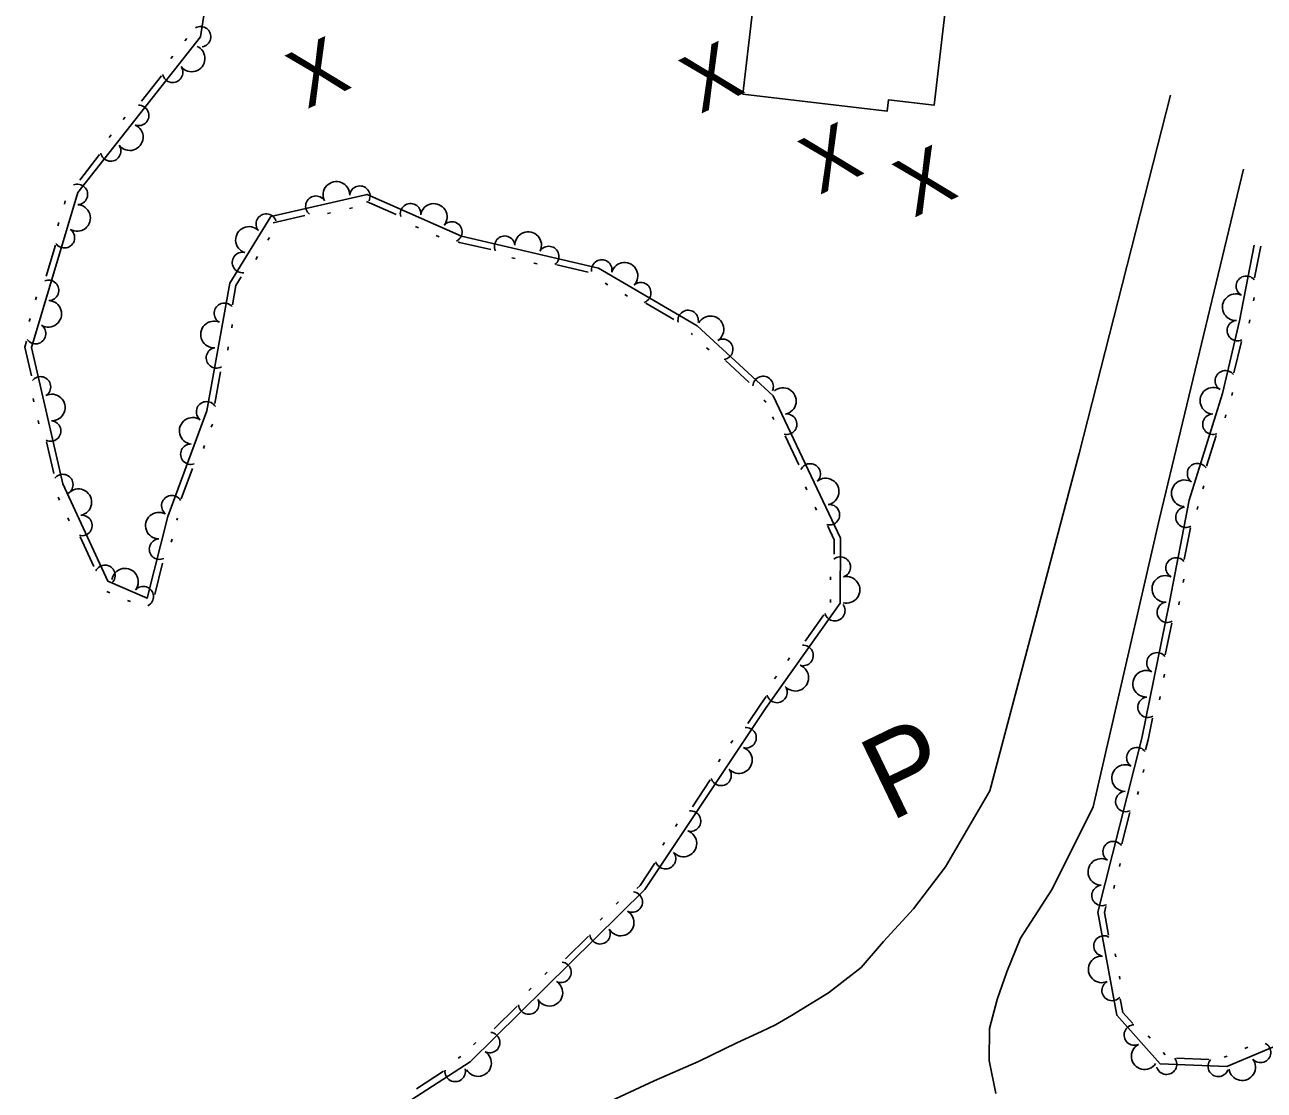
# Model space of a CAD drawing. Extents: x 2030130 to 2036320, y 723205 to 762423.
# Drawn here: x 2033439.8 to 2033597.2, y 761367.6 to 761502.9 of the extents above; entities that cross this region are included whole.
import ezdxf

# ---------------------------------------------------------------- set-up
doc = ezdxf.new("R2010")
doc.units = 0
for name, color, linetype in [('Draft_Station Labels Major', 7, 'Continuous'), ('Draft_Station Tics Major', 7, 'Continuous'), ('Exist Terrain Model Ground Surface', 7, 'Continuous'), ('Prop Horizontal Alignment Ramp', 7, 'Continuous')]:
    doc.layers.add(name, color=color, linetype=linetype)

msp = doc.modelspace()

# ---------------------------------------------------------------- linework, layer by layer
at = {"layer": 'Draft_Station Labels Major'}
for points in [[(2033525.39, 761371.23), (2033530.26, 761373.62), (2033533.37, 761375.05), (2033535.15, 761375.9), (2033537.18, 761377.07), (2033541.91, 761379.95), (2033546.04, 761383.19), (2033548.86, 761386.5), (2033552.7, 761390.64), (2033556.75, 761395.98), (2033562.4, 761405.6), (2033573.75, 761448.47), (2033585.35, 761493.96)], [(2033594.61, 761484.55), (2033583.93, 761440.18), (2033575.51, 761403.57), (2033570.32, 761393.14), (2033566.29, 761386.89), (2033564.53, 761382.64), (2033563.33, 761379.11), (2033562.33, 761375.43), (2033562.32, 761371.35), (2033563.15, 761367.2)], [(2033450.49, 761331), (2033472.55, 761343.63), (2033483.7, 761350.58), (2033494.36, 761356.54), (2033502.08, 761360.39), (2033511.2, 761364.83), (2033519.73, 761368.8), (2033525.39, 761371.23)]]:
    msp.add_lwpolyline(points, dxfattribs=at)
at = {"layer": 'Draft_Station Tics Major'}
for points in [[(2033464.52, 761516.87), (2033462.13, 761501.38), (2033446.55, 761481.58), (2033440.64, 761461.92), (2033444.62, 761444.59), (2033450.33, 761432.22), (2033455.34, 761430.07), (2033457.97, 761440.46), (2033462.94, 761453.88), (2033465.84, 761470.1), (2033471.07, 761478.54), (2033483.27, 761481.34), (2033495.28, 761476.04), (2033512.68, 761472), (2033525.2, 761464.67), (2033534.87, 761455.78), (2033543.43, 761437.68), (2033543.36, 761429.44), (2033533.88, 761416.05), (2033518.58, 761393.08), (2033496.38, 761371.21), (2033467.55, 761352.57)], [(2033460.39, 761501.16), (2033460.14, 761500.84)], [(2033458.62, 761498.91), (2033458.36, 761498.59)], [(2033457.16, 761496.4), (2033454.63, 761493.18)], [(2033452.53, 761491.17), (2033452.28, 761490.85)], [(2033450.76, 761488.92), (2033450.5, 761488.59)], [(2033449.3, 761486.41), (2033446.77, 761483.18)], [(2033444.94, 761480.52), (2033444.83, 761480.13)], [(2033481.04, 761479.57), (2033481.44, 761479.66)], [(2033483.21, 761480.47), (2033486.96, 761478.82)], [(2033471.36, 761477.76), (2033475.35, 761478.68)], [(2033478.24, 761478.92), (2033478.64, 761479.02)], [(2033444.12, 761477.77), (2033444, 761477.38)], [(2033489.42, 761477.28), (2033489.8, 761477.12)], [(2033443.69, 761474.9), (2033442.51, 761470.98)], [(2033470.66, 761475.54), (2033470.87, 761475.89)], [(2033492.05, 761476.12), (2033492.43, 761475.96)], [(2033494.84, 761475.34), (2033495.02, 761475.26), (2033498.98, 761474.34)], [(2033595.98, 761474.92), (2033594.12, 761465.29), (2033591.93, 761456.09), (2033587.72, 761442.52), (2033585.19, 761429.56), (2033581.69, 761412.29), (2033576.1, 761390.21), (2033578.5, 761377.11), (2033584.04, 761370.93), (2033592.47, 761370.59), (2033608.49, 761377.33)], [(2033596.79, 761474.77), (2033596.01, 761470.74)], [(2033469.15, 761473.1), (2033469.36, 761473.45)], [(2033501.68, 761473.29), (2033502.08, 761473.2)], [(2033504.48, 761472.64), (2033504.88, 761472.55)], [(2033507.37, 761472.39), (2033511.36, 761471.47)], [(2033466.18, 761467.32), (2033466.62, 761469.8), (2033467.29, 761470.88)], [(2033513.53, 761470.08), (2033513.88, 761469.87)], [(2033516.01, 761468.63), (2033516.36, 761468.42)], [(2033441.29, 761468.35), (2033441.17, 761467.95)], [(2033518.69, 761467.53), (2033522.23, 761465.46)], [(2033595.95, 761468.25), (2033595.87, 761467.85)], [(2033440.46, 761465.6), (2033440.34, 761465.2)], [(2033595.4, 761465.43), (2033595.32, 761465.02)], [(2033466.08, 761464.42), (2033466.15, 761464.82)], [(2033524.46, 761463.67), (2033524.6, 761463.55)], [(2033440.03, 761462.73), (2033439.8, 761461.95), (2033440.63, 761458.32)], [(2033594.34, 761462.68), (2033593.39, 761458.69)], [(2033465.57, 761461.59), (2033465.64, 761462)], [(2033526.41, 761461.88), (2033526.72, 761461.6)], [(2033528.81, 761460.24), (2033531.83, 761457.47)], [(2033463.94, 761454.8), (2033464.66, 761458.84)], [(2033593.22, 761456.2), (2033593.13, 761455.8)], [(2033440.87, 761455.43), (2033440.96, 761455.03)], [(2033533.66, 761455.22), (2033533.96, 761454.95)], [(2033441.51, 761452.63), (2033441.6, 761452.23)], [(2033534.77, 761453.12), (2033534.94, 761452.75)], [(2033592.38, 761453.37), (2033592.26, 761452.98)], [(2033463.47, 761451.78), (2033463.62, 761452.16)], [(2033442.55, 761449.93), (2033443.47, 761445.93)], [(2033462.48, 761449.08), (2033462.62, 761449.47)], [(2033536.37, 761450.7), (2033538.12, 761447)], [(2033591.13, 761450.75), (2033589.92, 761446.83)], [(2033459.67, 761442.69), (2033461.09, 761446.53)], [(2033538.97, 761444.23), (2033539.15, 761443.85)], [(2033589.58, 761444.36), (2033589.46, 761443.97)], [(2033444.05, 761442.89), (2033444.22, 761442.51)], [(2033540.2, 761441.63), (2033540.38, 761441.26)], [(2033588.82, 761441.73), (2033588.74, 761441.33)], [(2033445.25, 761440.28), (2033445.42, 761439.91)], [(2033459.11, 761439.98), (2033459.14, 761440.1), (2033459.2, 761440.24)], [(2033541.8, 761439.21), (2033542.61, 761437.5), (2033542.59, 761435.67)], [(2033587.87, 761439), (2033587.08, 761434.97)], [(2033446.83, 761437.85), (2033448.55, 761434.12)], [(2033458.41, 761437.19), (2033458.51, 761437.59)], [(2033456.3, 761430.53), (2033457.31, 761434.51)], [(2033542.16, 761432.8), (2033542.15, 761432.39)], [(2033587.01, 761432.48), (2033586.93, 761432.07)], [(2033450.21, 761430.94), (2033450.59, 761430.77)], [(2033452.85, 761429.8), (2033453.22, 761429.64)], [(2033542.13, 761429.93), (2033542.13, 761429.52)], [(2033586.46, 761429.66), (2033586.39, 761429.32), (2033586.38, 761429.25)], [(2033541.31, 761427.96), (2033538.94, 761424.61)], [(2033585.49, 761426.92), (2033584.67, 761422.9)], [(2033536.95, 761422.51), (2033536.71, 761422.17)], [(2033535.29, 761420.16), (2033535.05, 761419.83)], [(2033584.59, 761420.41), (2033584.5, 761420.01)], [(2033533.97, 761417.58), (2033533.21, 761416.51), (2033531.65, 761414.17)], [(2033584.02, 761417.59), (2033583.93, 761417.19)], [(2033583.04, 761414.86), (2033582.49, 761412.11), (2033582.16, 761410.82)], [(2033529.72, 761412.01), (2033529.49, 761411.67)], [(2033528.12, 761409.62), (2033527.9, 761409.28)], [(2033526.87, 761407), (2033524.6, 761403.59)], [(2033581.95, 761408.33), (2033581.85, 761407.93)], [(2033581.25, 761405.55), (2033581.15, 761405.15)], [(2033580.15, 761402.87), (2033579.14, 761398.89)], [(2033522.67, 761401.43), (2033522.44, 761401.09)], [(2033521.07, 761399.04), (2033520.85, 761398.7)], [(2033519.82, 761396.42), (2033517.95, 761393.61), (2033517.56, 761393.22)], [(2033578.94, 761396.4), (2033578.84, 761396.01)], [(2033578.24, 761393.62), (2033578.14, 761393.22)], [(2033515.22, 761391.5), (2033514.93, 761391.21)], [(2033577.13, 761390.94), (2033576.94, 761390.18), (2033577.48, 761387.27)], [(2033513.18, 761389.49), (2033512.89, 761389.2)], [(2033511.42, 761387.18), (2033508.5, 761384.3)], [(2033578.32, 761384.92), (2033578.4, 761384.52)], [(2033506.17, 761382.58), (2033505.87, 761382.29)], [(2033578.84, 761382.1), (2033578.91, 761381.69)], [(2033504.12, 761380.57), (2033503.83, 761380.28)], [(2033578.95, 761379.2), (2033579.27, 761377.48), (2033580.53, 761376.07)], [(2033502.36, 761378.26), (2033499.44, 761375.38)], [(2033582.48, 761374.51), (2033582.75, 761374.21)], [(2033497.11, 761373.66), (2033496.81, 761373.37)], [(2033584.4, 761372.38), (2033584.67, 761372.07)], [(2033594.78, 761372.9), (2033595.16, 761373.06)], [(2033495.17, 761371.9), (2033494.83, 761371.68)], [(2033586.1, 761371.67), (2033590.2, 761371.5)], [(2033592.14, 761371.78), (2033592.52, 761371.94)], [(2033492.99, 761370), (2033489.55, 761367.77)]]:
    msp.add_lwpolyline(points, dxfattribs=at)
for centre, radius, start, end in [((2033462.13, 761501.37), 1.3, 279.6475, 120.4441), ((2033460.99, 761498.61), 1.69, 217.7725, 65.845), ((2033458.57, 761496.86), 1.3, 192.5772, 33.3738), ((2033454.26, 761491.38), 1.3, 250.2437, 91.0403), ((2033453.13, 761488.62), 1.69, 217.7725, 65.845), ((2033450.71, 761486.87), 1.3, 192.5772, 33.3738), ((2033446.48, 761481.35), 1.3, 271.7173, 112.5138), ((2033479.38, 761481.29), 1.69, 358.9154, 206.9878), ((2033476.77, 761479.85), 1.3, 31.3865, 232.1831), ((2033482.36, 761481.13), 1.3, 333.7201, 174.5166), ((2033446.44, 761478.36), 1.69, 239.2461, 87.3186), ((2033488.8, 761478.9), 1.3, 354.6004, 195.397), ((2033491.75, 761478.49), 1.69, 322.1292, 170.2017), ((2033470.47, 761477.58), 1.3, 19.0011, 219.7977), ((2033494.05, 761476.58), 1.3, 296.9339, 137.7305), ((2033444.83, 761475.85), 1.3, 214.0508, 54.8474), ((2033468.27, 761475.57), 1.69, 44.1964, 252.2689), ((2033503.74, 761474.92), 1.69, 332.9051, 180.9775), ((2033500.76, 761474.77), 1.3, 5.3762, 206.1728), ((2033506.35, 761473.47), 1.3, 307.7098, 148.5063), ((2033467.45, 761472.7), 1.3, 76.6676, 277.4642), ((2033513.09, 761471.76), 1.3, 348.0658, 188.8624), ((2033515.98, 761471.02), 1.69, 315.5947, 163.6671), ((2033442.82, 761469.17), 1.3, 271.7173, 112.5138), ((2033518.04, 761468.86), 1.3, 290.3994, 131.196), ((2033594.97, 761469.69), 1.3, 39.8144, 240.611), ((2033593.62, 761467.03), 1.69, 65.0097, 273.0822), ((2033442.78, 761466.18), 1.69, 239.2461, 87.3186), ((2033465.15, 761466.25), 1.3, 40.6305, 241.427), ((2033463.84, 761463.57), 1.69, 65.8257, 273.8982), ((2033524.06, 761465.34), 1.3, 348.0658, 188.8624), ((2033526.89, 761464.22), 1.69, 303.3977, 151.4702), ((2033593.83, 761464.06), 1.3, 95.0689, 295.8655), ((2033441.17, 761463.67), 1.3, 214.0508, 54.8474), ((2033528.45, 761461.68), 1.3, 278.2024, 118.999), ((2033464.14, 761460.6), 1.3, 98.2969, 299.0935), ((2033592.31, 761457.68), 1.3, 37.4025, 238.199), ((2033441.79, 761456.91), 1.3, 301.3436, 142.1402), ((2033533.59, 761456.96), 1.3, 335.8689, 176.6655), ((2033443.23, 761454.29), 1.69, 268.8724, 116.9449), ((2033536.1, 761455.11), 1.69, 281.2658, 129.3383), ((2033590.78, 761455.15), 1.69, 58.7159, 266.7884), ((2033462.89, 761453.74), 1.3, 30.4269, 231.2234), ((2033461.12, 761451.33), 1.69, 55.6221, 263.6946), ((2033536.58, 761452.17), 1.3, 256.0706, 96.8671), ((2033590.72, 761452.17), 1.3, 91.1871, 291.9836), ((2033443.08, 761451.31), 1.3, 243.6771, 84.4737), ((2033460.89, 761448.36), 1.3, 88.0933, 288.8899), ((2033539.56, 761445.86), 1.3, 313.737, 154.5336), ((2033588.77, 761445.9), 1.3, 33.5206, 234.3172), ((2033444.63, 761444.51), 1.3, 301.3436, 142.1402), ((2033541.53, 761443.62), 1.69, 281.2658, 129.3383), ((2033587.14, 761443.4), 1.69, 58.7159, 266.7884), ((2033446.6, 761442.26), 1.69, 280.7746, 128.847), ((2033458.47, 761441.82), 1.3, 30.4269, 231.2234), ((2033542.01, 761440.67), 1.3, 256.0706, 96.8671), ((2033587.3, 761440.36), 1.3, 97.3659, 298.1625), ((2033447.06, 761439.31), 1.3, 255.5793, 96.3758), ((2033456.82, 761439.29), 1.69, 61.7723, 269.8448), ((2033456.91, 761436.3), 1.3, 94.2435, 295.0401), ((2033543.4, 761434.02), 1.3, 287.9449, 128.7415), ((2033449.98, 761432.98), 1.3, 313.2457, 154.0423), ((2033452.53, 761432.17), 1.69, 322.6667, 170.7392), ((2033586.04, 761433.92), 1.3, 39.6994, 240.496), ((2033544.19, 761431.14), 1.69, 255.4737, 103.5462), ((2033584.68, 761431.26), 1.69, 64.8947, 272.9672), ((2033454.84, 761430.28), 1.3, 297.4714, 138.268), ((2033542.69, 761428.49), 1.3, 195.4876, 36.2841), ((2033584.93, 761428.29), 1.3, 96.9775, 297.7741), ((2033538.66, 761422.8), 1.3, 253.154, 93.9506), ((2033583.62, 761421.86), 1.3, 39.311, 240.1076), ((2033537.67, 761419.98), 1.69, 220.6828, 68.7553), ((2033582.25, 761419.21), 1.69, 64.5063, 272.5788), ((2033535.35, 761418.11), 1.3, 195.4876, 36.2841), ((2033582.48, 761416.23), 1.3, 96.9775, 297.7741), ((2033531.42, 761412.35), 1.3, 254.7643, 95.5608), ((2033530.51, 761409.51), 1.69, 222.2931, 70.3655), ((2033581.06, 761409.83), 1.3, 36.5857, 237.3822), ((2033579.56, 761407.24), 1.69, 61.7809, 269.8534), ((2033528.24, 761407.57), 1.3, 197.0978, 37.8944), ((2033579.66, 761404.26), 1.3, 94.2521, 295.0487), ((2033524.37, 761401.77), 1.3, 254.7643, 95.5608), ((2033523.46, 761398.93), 1.69, 222.2931, 70.3655), ((2033578.05, 761397.9), 1.3, 36.5857, 237.3822), ((2033521.19, 761396.99), 1.3, 197.0978, 37.8944), ((2033576.55, 761395.32), 1.69, 61.7809, 269.8534), ((2033576.64, 761392.33), 1.3, 94.2521, 295.0487), ((2033516.96, 761391.49), 1.3, 242.9904, 83.7869), ((2033515.49, 761388.89), 1.69, 210.5192, 58.5917), ((2033512.87, 761387.46), 1.3, 185.3239, 26.1205), ((2033576.89, 761385.91), 1.3, 61.1418, 261.9384), ((2033507.91, 761382.57), 1.3, 242.9904, 83.7869), ((2033576.6, 761382.94), 1.69, 86.3371, 294.4096), ((2033506.44, 761379.97), 1.69, 210.5192, 58.5917), ((2033577.92, 761380.26), 1.3, 118.8083, 319.6049), ((2033503.81, 761378.54), 1.3, 185.3239, 26.1205), ((2033580.74, 761374.61), 1.3, 92.642, 293.4386), ((2033498.85, 761373.65), 1.3, 242.9904, 83.7869), ((2033497.38, 761371.05), 1.69, 210.5192, 58.5917), ((2033582.05, 761371.92), 1.69, 117.8373, 325.9098), ((2033596.77, 761372.4), 1.3, 221.2453, 62.0418), ((2033584.84, 761370.9), 1.3, 196.0945, 36.891), ((2033591.4, 761370.63), 1.3, 138.428, 339.2246), ((2033594.44, 761370.53), 1.69, 188.7741, 36.8466), ((2033494.47, 761369.98), 1.3, 173.6745, 14.471)]:
    msp.add_arc(centre, radius, start, end, dxfattribs=at)
at = {"layer": 'Exist Terrain Model Ground Surface'}
msp.add_lwpolyline([(2033559.17, 761525.61), (2033555.33, 761492.7), (2033549.52, 761493.38), (2033549.35, 761491.94), (2033531.02, 761494.08), (2033532.63, 761507.89), (2033499.17, 761511.79), (2033501.96, 761535.74), (2033555.28, 761529.53), (2033554.88, 761526.11)], close=True, dxfattribs=at)

# ---------------------------------------------------------------- texts
at = {"layer": 'Draft_Station Tics Major'}
for p in [(2033475.61, 761492.14), (2033525.58, 761491.53), (2033540.72, 761481.25), (2033552.71, 761478.35)]:
    msp.add_text('X', height=7.38, rotation=25.7434, dxfattribs=at).set_placement(p)
at = {"layer": 'Prop Horizontal Alignment Ramp'}
msp.add_text('P', height=10.66, rotation=25.7434, dxfattribs=at).set_placement((2033549.7, 761401.64))

doc.saveas('drawing.dxf')
